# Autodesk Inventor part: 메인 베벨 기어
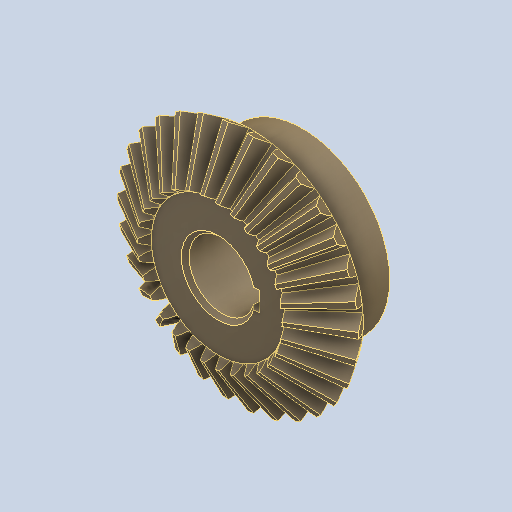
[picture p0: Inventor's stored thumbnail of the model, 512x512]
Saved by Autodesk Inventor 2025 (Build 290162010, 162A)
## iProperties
Created: 2024-07
Part Number: 메인 베벨 기어
Material: 강철, 탄소
Document SubType Name: Modeling
Designer: 계정
Density: 7.87 g/cm^3
Appearance: 기본값
Author: jhkim
Revision Number: 1
Sending System: Autodesk Inventor 2025
Preprocessor: ST-DEVELOPER v20
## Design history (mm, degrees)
feature "Solid1"
node "솔리드1"
